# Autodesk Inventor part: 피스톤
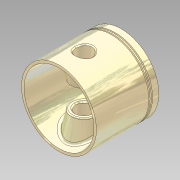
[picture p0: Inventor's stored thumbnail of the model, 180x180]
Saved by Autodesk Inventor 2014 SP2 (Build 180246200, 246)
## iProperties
Manager: KYOUNG IL JANG
Company: 한국ATC센터
Created: 2012-10
Part Number: 피스톤
Document SubType Name: Modeling
Density: 1 g/cm^3
Checked By: KYOUNG IL JANG
Vendor: CBT Solutions
Designer: KYOUNG IL JANG
Material: 일반
Appearance: _시험_금속-티타늄(광택)
Author: KYOUNG IL JANG
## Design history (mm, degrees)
sketch "스케치1"
  geometry: L1 (0, 0)-(0, 50); L2 (0, 50)-(30, 50); L3 (30, 50)-(30, 45); L4 (30, 45)-(28, 45); L5 (28, 45)-(28, 44); L6 (28, 44)-(30, 44); L7 (30, 44)-(30, 43); L8 (30, 43)-(28, 43); L9 (28, 43)-(28, 42); L10 (28, 42)-(30, 42); L11 (30, 42)-(30, 0); L12 (30, 0)-(28, 0); L13 (28, 0)-(23, 45); L14 (23, 45)-(0, 45)
  constraints: 28 end point, 10 parallel, 5 collinear, 2 perpendicular, 2 point on line, 1 vertical
  dimensions: "d0" = 50 distance of L1.start L1.end; "d1" = 60 diameter of L3 L1; "d2" = 5 distance between parallel lines of L2 L14; "d3" = 2 distance of L11.end L12.end; "d5" = 5 distance of L2.end L3.end; "d6" = 1 distance of L4.end L5.end; "d7" = 2 distance of L9.end L10.end; "d26" = 46 diameter of L13.end L1
revolve "회전1" sketch "스케치1" stored, may be unused: angle "d8" = 90 deg
node "작업 평면1"
sketch "스케치2"
  geometry: L1 (-28, 0)-(28, 0) reference; C1 r 10 at (0, 20); C2 r 6.5 at (0, 20); 1 further point
  constraints: 2 centre point, 1 coincident, 1 vertical alignment
  dimensions: "d10" = 20 diameter of C1; "d13" = 20 distance from line of C1.centre L1; "d14" = 13 diameter of C2
extrude "돌출1" join sketch "스케치2" stored distance "d11" = 10; taper "d12" = 12 deg
extrude "돌출2" cut sketch "스케치2" stored distance "d15" = 10; taper "d16" = 0 deg
fillet "모깎기1" dims "d17" = 2, "d21" = 3
chamfer "모따기1" distance "d18" = 1; stored, may be unused: second distance "d19" = 2, angle "d20" = 45 deg
chamfer "모따기2" distance "d22" = 1; stored, may be unused: second distance "d23" = 2, angle "d24" = 45 deg
fillet "모깎기2" dims "d25" = 1
node "솔리드1"
mirror "대칭1"
